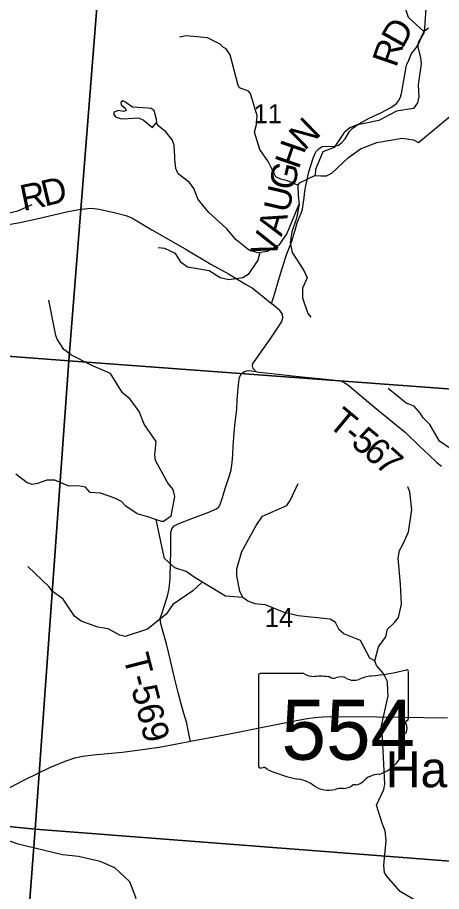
# Model space of a CAD drawing. Extents: x 1878108 to 2183446, y 146837 to 508383.
# Drawn here: x 2004746 to 2009673, y 326520 to 336667 of the extents above; entities that cross this region are included whole.
import ezdxf

# ---------------------------------------------------------------- set-up
doc = ezdxf.new("R2010")
doc.units = 0
for name, color, linetype in [('GM_X_Major_Lake', 7, 'Continuous'), ('GM_X_Minor_River', 7, 'Continuous'), ('GM_X_Section', 7, 'Continuous'), ('GM_X_Section_Text', 7, 'Continuous'), ('GM_X_State_Location', 7, 'Continuous'), ('GM_X_State_Route', 7, 'Continuous'), ('GM_X_State_Shield', 7, 'Continuous'), ('GM_X_Township_Road', 7, 'Continuous'), ('GM_X_Township_Road_Text', 7, 'Continuous'), ('GM_X_Unincorporated_Text', 7, 'Continuous')]:
    doc.layers.add(name, color=color, linetype=linetype)

msp = doc.modelspace()

# ---------------------------------------------------------------- linework, layer by layer
at = {"layer": 'GM_X_Major_Lake'}
msp.add_line((2009404, 335215), (2010506, 336132), dxfattribs=at)
msp.add_lwpolyline([(2009494, 336834), (2009476, 336543), (2009465, 336489), (2009401, 336375), (2009397, 336325), (2009429, 336198), (2009435, 336130), (2009402, 335886), (2009410, 335745), (2009392, 335677), (2009346, 335611), (2009149, 335578), (2008945, 335469), (2008682, 335416), (2008606, 335386), (2008540, 335332), (2008426, 335157), (2008295, 335105), (2008209, 334900), (2008205, 334832), (2008269, 334828), (2008335, 334830), (2008397, 334858), (2008590, 335041), (2008730, 335142), (2008920, 335217), (2009215, 335264), (2009345, 335248), (2009404, 335215)], dxfattribs=at)
at = {"layer": 'GM_X_Minor_River'}
for points in [[(2008660, 337675), (2008730, 337545), (2008788, 337489), (2008932, 337398), (2009010, 337310), (2009150, 337056), (2009207, 336929), (2009227, 336841), (2009285, 336671), (2009467, 336505)], [(2008004, 334719), (2007882, 334772), (2007804, 334788), (2007748, 334818), (2007660, 334994), (2007560, 335134), (2007500, 335334), (2007524, 335423), (2007530, 335523), (2007454, 335785), (2007430, 335813), (2007326, 335851), (2007308, 335877), (2007217, 336233), (2007169, 336303), (2007141, 336319), (2007101, 336355), (2006953, 336429), (2006706, 336454), (2006628, 336438)], [(2006263, 335613), (2006083, 335624), (2005995, 335688), (2005969, 335700), (2005945, 335680), (2005951, 335652), (2005999, 335614), (2006007, 335586), (2005979, 335576), (2005920, 335588), (2005866, 335568), (2005864, 335540), (2005884, 335514), (2005942, 335492), (2005974, 335490), (2006149, 335502), (2006207, 335478), (2006313, 335388), (2006366, 335450)], [(2006366, 335450), (2006361, 335481), (2006335, 335587), (2006299, 335611), (2006263, 335613)], [(2008016, 334494), (2007877, 334160), (2007783, 334025), (2007646, 333951), (2007544, 333935), (2007440, 333961), (2007286, 334084), (2007176, 334218), (2006970, 334402), (2006846, 334554), (2006796, 334682), (2006744, 334752), (2006612, 334852), (2006586, 334914), (2006575, 335018), (2006575, 335052), (2006565, 335185), (2006543, 335247), (2006471, 335341), (2006389, 335403), (2006369, 335429), (2006366, 335450)], [(2008205, 334832), (2008020, 334743), (2008004, 334719), (2008008, 334600), (2008017, 334494), (2007987, 334338), (2007935, 334180), (2007915, 334054), (2007939, 333937), (2008071, 333729), (2008111, 333645), (2008058, 333525), (2008056, 333411), (2008118, 333231), (2008154, 333187)], [(2004554, 334376), (2004750, 334422), (2004916, 334495)], [(2007561, 333937), (2007540, 333849), (2007428, 333682), (2007364, 333644), (2007200, 333620), (2007102, 333646), (2006973, 333725), (2006721, 333767), (2006653, 333817), (2006581, 333927), (2006459, 333985), (2006379, 333993)], [(2006298, 330858), (2006416, 330821), (2006444, 330819), (2006530, 330883), (2006574, 331105), (2006554, 331185), (2006502, 331253), (2006480, 331283), (2006350, 331525), (2006340, 331591), (2006357, 331746), (2006329, 331782), (2006219, 331944), (2006159, 332094), (2006055, 332234), (2005991, 332288), (2005965, 332308), (2005827, 332534), (2005611, 332626), (2005365, 332749), (2005285, 332813), (2005207, 332933), (2005191, 332973), (2005109, 333386)], [(2009786, 331654), (2009648, 331748), (2009538, 331940), (2009458, 332018), (2009428, 332068), (2009354, 332154), (2009260, 332190), (2009054, 332359)], [(2006298, 330858), (2006137, 330904), (2006005, 330992), (2005955, 331046), (2005879, 331088), (2005711, 331146), (2005589, 331154), (2005535, 331214), (2005451, 331229), (2005343, 331225), (2005181, 331295), (2005087, 331295), (2004977, 331255), (2004917, 331246), (2004860, 331264), (2004728, 331364)], [(2009408, 326392), (2009192, 326522), (2009032, 326702), (2009010, 326742), (2009002, 326822), (2009028, 327114), (2009016, 327224), (2008988, 327300), (2008918, 327521), (2009001, 327703), (2009013, 327767), (2008985, 328306), (2008976, 328444), (2009052, 328791), (2009050, 328845), (2009044, 328957), (2008998, 329049), (2008916, 329143), (2008898, 329197), (2008838, 329229), (2008730, 329433), (2008538, 329511), (2008482, 329557), (2008440, 329643), (2008378, 329681), (2008008, 329722), (2007846, 329760), (2007626, 329849), (2007538, 329855), (2007506, 329861), (2007422, 329891), (2007364, 329935), (2007328, 330005), (2007296, 330183), (2007296, 330267), (2007354, 330468), (2007519, 330770), (2007593, 330879), (2007875, 331001), (2007913, 331060), (2008008, 331256)], [(2008897, 329197), (2008939, 329361), (2009025, 329475), (2009045, 329564), (2009127, 329644), (2009171, 329700), (2009207, 329854), (2009194, 330089), (2009168, 330389), (2009186, 330477), (2009226, 330555), (2009288, 330696), (2009329, 330952), (2009305, 331160), (2009281, 331218)], [(2007364, 329935), (2007161, 329947), (2006811, 330160), (2006707, 330236), (2006573, 330276), (2006455, 330386), (2006437, 330454), (2006357, 330840)], [(2006890, 330112), (2006785, 330010), (2006551, 329851), (2006474, 329741), (2006258, 329565), (2005998, 329482), (2005936, 329496), (2005800, 329570), (2005681, 329590), (2005487, 329657), (2005407, 329717), (2005275, 329915), (2005149, 330007), (2005113, 330057), (2004865, 330293)], [(2006302, 325036), (2006253, 325202), (2006137, 325304), (2006106, 325358), (2006088, 325530), (2006155, 325966), (2006171, 326148), (2006122, 326451), (2006051, 326634), (2005879, 326794), (2005708, 326868), (2005454, 326925), (2005270, 326945), (2004756, 327070), (2004442, 327178), (2004225, 327231), (2004138, 327266)]]:
    msp.add_lwpolyline(points, dxfattribs=at)
at = {"layer": 'GM_X_Section'}
for points in [[(2000503, 338421), (2005767, 338056), (2005343, 332682), (2000093, 333079)], [(2011013, 337645), (2010635, 332291), (2005343, 332682), (2005767, 338056)], [(2005343, 332682), (2004952, 327244), (1999689, 327768), (2000093, 333079)], [(2005343, 332682), (2010635, 332291), (2010226, 326837), (2004952, 327244)], [(1999689, 327768), (2004952, 327244), (2004547, 321948), (1999255, 322337)], [(2010226, 326837), (2009823, 321447), (2004547, 321948), (2004952, 327244)]]:
    msp.add_lwpolyline(points, close=True, dxfattribs=at)
at = {"layer": 'GM_X_State_Route'}
msp.add_lwpolyline([(2004470, 327631), (2004806, 327806), (2005001, 327903), (2005121, 327960), (2005299, 328033), (2005411, 328070), (2005507, 328092), (2005625, 328107), (2005967, 328139), (2006252, 328175), (2006391, 328194), (2006598, 328234), (2006757, 328264), (2007152, 328340), (2007811, 328471), (2008087, 328524), (2008202, 328540), (2008295, 328549), (2008388, 328551), (2008919, 328546), (2009741, 328536)], dxfattribs=at)
at = {"layer": 'GM_X_State_Shield'}
for p, q in [((2009287, 328524), (2009287, 329076)), ((2007547, 329032), (2007547, 327975)), ((2008074, 329050), (2007564, 329050)), ((2009287, 328524), (2009287, 328524))]:
    msp.add_line(p, q, dxfattribs=at)
for centre, major_axis, start_param, end_param in [((2008667, 330491), (1845, 0), 4.814394, 5.042369), ((2009268, 329079), (19.4, 0), 6.141152, 7.989035), ((2007567, 329034), (20.2, 0), 1.712693, 3.28349), ((2008195, 329173), (196, 0), 4.042523, 4.731795), ((2008260, 328457), (702, 0), 1.404758, 1.657858), ((2008419, 329040), (56.4, 0), 3.836095, 5.185415), ((2008502, 328918), (117, 0), 0.950623, 2.079405), ((2008653, 329085), (141, 0), 4.081561, 5.145723), ((2008903, 328727), (371, 0), 1.699011, 2.107814), ((2009283, 328483), (30, 0), 1.883978, 3.671073), ((2009092, 328413), (180, 0), 5.934695, 6.695948), ((2009266, 328521), (20.7, 0), 5.05454, 6.418171), ((2009357, 328292), (131, 0), 2.387724, 3.262537), ((2008771, 328222), (462, 0), 5.101752, 6.440018), ((2007567, 327973), (20.3, 0), 3.00124, 4.508301), ((2007570, 328081), (155, 0), 4.665946, 4.897461), ((2007602, 327914), (56, 0), 0.519207, 1.627899), ((2008308, 328864), (1333, 0), 4.195997, 4.488961), ((2008965, 327679), (253, 0), 1.647645, 2.488434), ((2007911, 327501), (417, 0), 0.823519, 1.323587), ((2008362, 327909), (265, 0), 4.026481, 4.996735), ((2008534, 327830), (141, 0), 4.691044, 5.507374), ((2008662, 327728), (39.7, 0), 1.147584, 2.315152), ((2008645, 327873), (149, 0), 4.937069, 5.64225), ((2008515, 327544), (217, 0), 1.495662, 1.94098)]:
    msp.add_ellipse(centre, major_axis=major_axis, ratio=0.8, start_param=start_param, end_param=end_param, dxfattribs=at)
at = {"layer": 'GM_X_Township_Road'}
for points in [[(2008236, 335131), (2008247, 335142), (2008286, 335168), (2008334, 335172), (2008415, 335170), (2008477, 335185), (2008516, 335214), (2008552, 335257), (2008604, 335343), (2008635, 335376), (2008711, 335433), (2008832, 335498), (2008967, 335560), (2009093, 335624), (2009151, 335668), (2009173, 335698), (2009194, 335740), (2009206, 335785), (2009245, 336003), (2009267, 336113), (2009293, 336171), (2009324, 336249), (2009377, 336315), (2009413, 336373), (2009444, 336453), (2009475, 336512), (2009521, 336546)], [(2007516, 332555), (2007483, 332593), (2007477, 332621), (2007482, 332649), (2007507, 332685), (2007579, 332785), (2007682, 332932), (2007736, 333012), (2007789, 333093), (2007818, 333137), (2007830, 333178), (2007825, 333221), (2007795, 333263), (2007697, 333348), (2007724, 333429), (2007791, 333652), (2007855, 333865), (2007875, 333922), (2007929, 334059), (2007971, 334197), (2007995, 334284), (2008047, 334408), (2008058, 334441), (2008075, 334575), (2008086, 334649), (2008100, 334732), (2008130, 334876), (2008182, 335034), (2008211, 335106), (2008236, 335131)], [(2004597, 334255), (2004778, 334288), (2005038, 334345), (2005314, 334409), (2005484, 334442), (2005605, 334453), (2005697, 334440), (2005886, 334398), (2006005, 334369), (2006073, 334341), (2006306, 334203), (2006696, 333980), (2006993, 333803), (2007199, 333689), (2007395, 333572), (2007471, 333527), (2007592, 333431), (2007697, 333348)], [(2006757, 328264), (2006744, 328316), (2006725, 328413), (2006713, 328476), (2006699, 328526), (2006680, 328588), (2006653, 328683), (2006618, 328813), (2006571, 329001), (2006522, 329201), (2006476, 329394), (2006439, 329529), (2006412, 329626), (2006405, 329695), (2006422, 329745), (2006449, 329829), (2006489, 329947), (2006507, 330035), (2006520, 330159), (2006523, 330340), (2006529, 330461), (2006527, 330576), (2006526, 330688), (2006540, 330731), (2006568, 330765), (2006612, 330790), (2006770, 330850), (2006971, 330924), (2007058, 330962), (2007085, 330984), (2007102, 331013), (2007123, 331081), (2007164, 331212), (2007211, 331348), (2007230, 331417), (2007241, 331500), (2007249, 331590), (2007253, 331691), (2007263, 331844), (2007276, 331967), (2007293, 332116), (2007299, 332225), (2007311, 332362), (2007316, 332436), (2007325, 332490), (2007350, 332534), (2007385, 332557), (2007425, 332567), (2007466, 332564), (2007516, 332555)], [(2007516, 332555), (2007553, 332548), (2007776, 332525), (2007943, 332507), (2008130, 332486), (2008328, 332466), (2008472, 332454), (2008509, 332445), (2008548, 332426), (2008599, 332389), (2008898, 332138), (2009149, 331935), (2009254, 331847), (2009414, 331695), (2009528, 331584), (2009617, 331499), (2009673, 331459)]]:
    msp.add_lwpolyline(points, dxfattribs=at)

# ---------------------------------------------------------------- texts
at = {"layer": 'GM_X_Section_Text'}
for s, p in [('11', (2007490, 335439)), ('14', (2007620, 329589))]:
    msp.add_text(s, height=221, rotation=0, dxfattribs=at).set_placement(p)
at = {"layer": 'GM_X_State_Location'}
msp.add_text('554', height=1, rotation=0, dxfattribs=at).set_placement((2008044, 328361))
for s in ['s', 'r']:
    msp.add_text(s, height=1, dxfattribs=at).set_placement((2008397, 328433))
at = {"layer": 'GM_X_State_Shield'}
msp.add_text('554', height=696.1, dxfattribs=at).set_placement((2007813, 328050))
at = {"layer": 'GM_X_Township_Road_Text'}
for s, rotation, p in [('D', 60.8617, (2009220, 336297)), ('R', 70.9813, (2009145, 336077)), ('N', 44.5505, (2008081, 335113)), ('H', 70.8042, (2008013, 334895)), ('G', 76.8773, (2007955, 334646)), ('R', 11.6525, (2004812, 334419)), ('D', 13.5876, (2005063, 334471)), ('U', 76.8777, (2007896, 334388)), ('A', 73.4322, (2007815, 334116)), ('V', 71.781, (2007730, 333857)), ('T', 320.1876, (2008340, 331932)), ('5', 320.0275, (2008607, 331710)), ('-', 320.165, (2008513, 331789)), ('6', 319.6251, (2008748, 331591)), ('7', 318.1404, (2008888, 331473)), ('T-569', 284.3062, (2005973, 329244))]:
    msp.add_text(s, height=300, rotation=rotation, dxfattribs=at).set_placement(p)
at = {"layer": 'GM_X_Unincorporated_Text'}
msp.add_text('Harrisburg', height=417, rotation=0, dxfattribs=at).set_placement((2009026, 327730))

doc.saveas('drawing.dxf')
